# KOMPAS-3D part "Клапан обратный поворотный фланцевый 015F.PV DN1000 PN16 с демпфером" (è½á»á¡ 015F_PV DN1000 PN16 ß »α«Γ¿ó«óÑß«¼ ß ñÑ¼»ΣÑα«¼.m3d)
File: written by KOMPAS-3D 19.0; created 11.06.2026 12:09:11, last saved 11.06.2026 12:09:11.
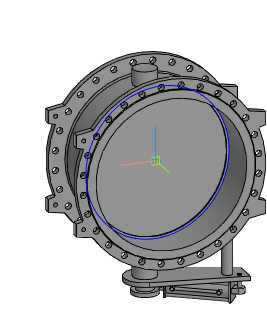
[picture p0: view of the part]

Document properties: Автор: Энергия; Полное имя файла: Z:\3.Личные\kachalov\001_3d для проектировщиков\5.5 Тип 015F.PV Клапан обратный поворотный с двумя эксцентриками\_stp_Клапан 015F.PV DN300-DN1200 с противовесом с демпфером\Клапан 015F_PV DN1000 PN16 с противовесом с демпфером.m3d

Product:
- Part/product: Клапан обратный поворотный фланцевый 015F.PV DN1000 PN16 с демпфером

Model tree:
1. Операция без истории:1
2. Сплайн:1
     Координата Y = 30; Координата Z = 500; Вес = 1; Координата X = 1000; Координата Y = 161.652; Координата Z = 500; Вес = 0.333333; Координата X = 1000; Координата Y = 161.652; Координата Z = -500; Вес = 0.333333; Координата Y = 30; Координата Z = -500; Вес = 1; Координата X = -1000; Координата Y = -101.652; Координата Z = -500; Вес = 0.333333; Координата X = -1000; Координата Y = -101.652; Координата Z = 500; Вес = 0.333333; Порядок = 4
